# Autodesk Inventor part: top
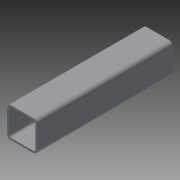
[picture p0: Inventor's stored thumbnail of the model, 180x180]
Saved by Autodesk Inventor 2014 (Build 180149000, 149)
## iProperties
Created: 2008-04
Part Number: top
Document SubType Name: Modeling
Designer: Jayson Martinez
Density: 1 g/cm^3
Material: Generic
Appearance: Default
Author: Jayson Martinez
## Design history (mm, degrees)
sketch "Sketch1"
  geometry: L1 (6.35, 0)-(44.45, 0); L2 (50.8, 6.35)-(50.8, 44.45); L3 (44.45, 50.8)-(6.35, 50.8); L4 (0, 44.45)-(0, 6.35); L5 (3.175, 6.35)-(3.175, 44.45); L6 (6.35, 47.625)-(44.45, 47.625); L7 (47.625, 44.45)-(47.625, 6.35); L8 (44.45, 3.175)-(6.35, 3.175); A1 r 6.35 centre (6.35, 44.45) between (6.35, 50.8) and (0, 44.45); A2 r 6.35 centre (44.45, 44.45) between (50.8, 44.45) and (44.45, 50.8); A3 r 6.35 centre (44.45, 6.35) between (44.45, 0) and (50.8, 6.35); A4 r 6.35 centre (6.35, 6.35) between (0, 6.35) and (6.35, 0); A5 r 3.175 centre (6.35, 44.45) between (6.35, 47.625) and (3.175, 44.45); A6 r 3.175 centre (44.45, 44.45) between (47.625, 44.45) and (44.45, 47.625); A7 r 3.175 centre (44.45, 6.35) between (44.45, 3.175) and (47.625, 6.35); A8 r 3.175 centre (6.35, 6.35) between (3.175, 6.35) and (6.35, 3.175); 3 further points
  constraints: 16 end point, 16 point on circle, 8 centre point, 8 tangent, 6 point on line, 4 parallel, 3 equal radius, 2 perpendicular, 1 horizontal, 7 other
  dimensions: "d0" = 50.8 distance of point (0, 0) point (50.8, 0) (= MemberWidth); "d1" = 50.8 distance of point (0, 50.8) point (0, 0) (= d0); "d2" = 6.35 radius of A1 (= 2 x MemberThickness); "d3" = 3.175 distance between parallel lines of L2 L7 (= MemberThickness)
extrude "Extrusion1" new body sketch "Sketch1" distance "d4" = 228.6 (= -0.5 x MemberWidth + 0.5 x HorizontalLength); taper "d5" = 0 deg
workplane "Work Plane1"
body "Solid1"
other parameters: "d7" = -25.4 (= -0.5 x MemberWidth), "MemberThickness" = 3.175, "MemberWidth" = 50.8, "HorizontalLength" = 508
